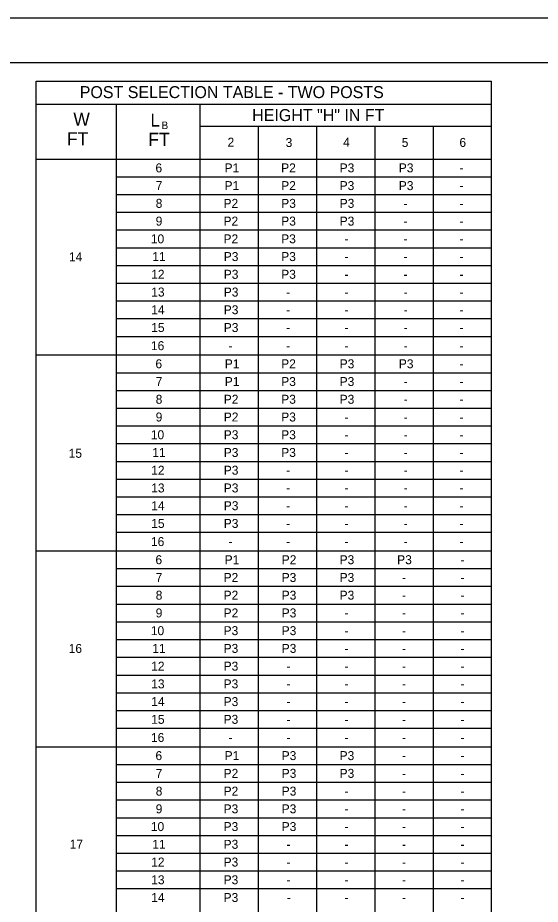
# Model space of a CAD drawing. Extents: x -2340 to 628, y -879 to 309.
# Drawn here: x -912.9 to -738, y -581.5 to -284.6 of the extents above; entities that cross this region are included whole.
import ezdxf

# ---------------------------------------------------------------- set-up
doc = ezdxf.new("R2010")
doc.units = 0
for name, color, linetype in [('Level 1', 7, 'Continuous'), ('Level 2', 7, 'Continuous'), ('Level 30', 7, 'Continuous'), ('PLT-BNDY', 7, 'Continuous')]:
    doc.layers.add(name, color=color, linetype=linetype)

msp = doc.modelspace()

# ---------------------------------------------------------------- linework, layer by layer
at = {"layer": 'Level 1'}
for p, q in [((-1077.39, -299.56), (-291.39, -299.56)), ((-906.65, -791.15), (-906.65, -305.86)), ((-906.65, -305.86), (-754.31, -305.86)), ((-754.31, -791.15), (-754.31, -305.86)), ((-906.65, -313.54), (-754.31, -313.54)), ((-879.85, -791.15), (-879.85, -313.54)), ((-851.84, -791.15), (-851.84, -313.54)), ((-832.34, -791.15), (-832.34, -320.88)), ((-812.83, -791.15), (-812.83, -320.88)), ((-793.32, -791.15), (-793.32, -320.88)), ((-773.81, -791.15), (-773.81, -320.88)), ((-906.65, -331.88), (-754.31, -331.88)), ((-813.5, -331.88), (-777.86, -331.88)), ((-879.85, -337.82), (-754.31, -337.82)), ((-879.85, -343.76), (-754.31, -343.76)), ((-879.85, -349.7), (-754.31, -349.7)), ((-879.85, -355.64), (-754.31, -355.64)), ((-879.85, -361.58), (-754.31, -361.58)), ((-879.85, -367.52), (-754.31, -367.52)), ((-879.85, -373.46), (-754.31, -373.46)), ((-879.85, -379.4), (-754.31, -379.4)), ((-879.85, -385.34), (-754.31, -385.34)), ((-879.85, -391.28), (-754.31, -391.28)), ((-906.65, -397.49), (-754.31, -397.49)), ((-879.85, -403.43), (-754.31, -403.43)), ((-879.85, -409.37), (-754.31, -409.37)), ((-879.85, -415.31), (-754.31, -415.31)), ((-879.85, -421.25), (-754.31, -421.25)), ((-879.85, -427.19), (-754.31, -427.19)), ((-879.85, -433.13), (-754.31, -433.13)), ((-879.85, -439.07), (-754.31, -439.07)), ((-879.85, -445.01), (-754.31, -445.01)), ((-879.85, -450.95), (-754.31, -450.95)), ((-879.85, -456.89), (-754.31, -456.89)), ((-906.65, -463.1), (-754.31, -463.1)), ((-879.85, -469.04), (-754.31, -469.04)), ((-879.85, -474.98), (-754.31, -474.98)), ((-813.5, -474.98), (-777.86, -474.98)), ((-777.86, -474.98), (-754.31, -474.98)), ((-879.85, -480.92), (-754.31, -480.92)), ((-879.85, -486.86), (-754.31, -486.86)), ((-879.85, -492.8), (-754.31, -492.8)), ((-879.85, -498.74), (-754.31, -498.74)), ((-879.85, -504.68), (-754.31, -504.68)), ((-879.85, -510.62), (-754.31, -510.62)), ((-879.85, -516.56), (-754.31, -516.56)), ((-879.85, -522.5), (-754.31, -522.5)), ((-906.65, -528.71), (-754.31, -528.71)), ((-879.85, -534.65), (-754.31, -534.65)), ((-879.85, -540.59), (-754.31, -540.59)), ((-879.85, -546.53), (-754.31, -546.53)), ((-879.85, -552.47), (-754.31, -552.47)), ((-879.85, -558.41), (-754.31, -558.41)), ((-879.85, -564.35), (-754.31, -564.35)), ((-879.85, -570.29), (-754.31, -570.29)), ((-879.85, -576.23), (-754.31, -576.23))]:
    msp.add_line(p, q, dxfattribs=at)
at = {"layer": 'Level 2'}
msp.add_line((-851.84, -320.88), (-754.31, -320.88), dxfattribs=at)
at = {"layer": 'PLT-BNDY'}
msp.add_lwpolyline([(-1117.39, -284.56), (-276.39, -284.56), (-276.39, -878.56), (-1117.39, -878.56)], close=True, dxfattribs=at)

# ---------------------------------------------------------------- texts
at = {"layer": 'Level 1'}
for s, height, p in [('POST SELECTION TABLE - TWO POSTS', 4.003, (-892.12, -311.48)), ('W', 4.37, (-894.25, -320.74)), ('L', 4.3, (-868.46, -321.01)), ('HEIGHT "H" IN FT', 4.003, (-834.42, -319.17)), ('B', 2.5, (-864.76, -321.84)), ('FT', 4.375, (-896.42, -327.3)), ('FT', 4.375, (-869.16, -327.47)), ('2', 3, (-842.66, -327.74)), ('3', 3, (-823.22, -327.84)), ('4', 3, (-803.98, -327.74)), ('5', 3, (-784.39, -327.84)), ('6', 3, (-765.08, -327.82)), ('P1', 3, (-843.67, -336.35)), ('P2', 3, (-824.72, -336.35)), ('P3', 3, (-805.15, -336.35)), ('P3', 3, (-785.37, -336.35)), ('-', 3, (-765.05, -336.35)), ('P1', 3, (-843.67, -342.29)), ('P2', 3, (-824.71, -342.29)), ('P3', 3, (-805.15, -342.29)), ('P3', 3, (-785.37, -342.29)), ('-', 3, (-765.05, -342.29)), ('P2', 3, (-844.01, -348.23)), ('P3', 3, (-824.71, -348.23)), ('P3', 3, (-805.15, -348.23)), ('-', 3, (-783.75, -348.23)), ('-', 3, (-765.05, -348.23)), ('P2', 3, (-844.01, -354.17)), ('P3', 3, (-824.71, -354.17)), ('P3', 3, (-805.15, -354.17)), ('-', 3, (-783.75, -354.17)), ('-', 3, (-765.05, -354.17)), ('P2', 3, (-844.01, -360.11)), ('P3', 3, (-824.71, -360.11)), ('-', 3, (-803.53, -360.11)), ('-', 3, (-783.75, -360.11)), ('-', 3, (-765.05, -360.11)), ('14', 3, (-895.73, -366.13)), ('P3', 3, (-843.93, -366.05)), ('P3', 3, (-824.71, -366.05)), ('-', 3, (-803.53, -366.05)), ('-', 3, (-783.75, -366.05)), ('-', 3, (-765.05, -366.05)), ('P3', 3, (-843.93, -371.99)), ('P3', 3, (-824.71, -371.99)), ('-', 3, (-803.53, -371.99)), ('-', 3, (-783.75, -371.99)), ('-', 3, (-765.05, -371.99)), ('P3', 3, (-843.93, -377.93)), ('-', 3, (-823.09, -377.93)), ('-', 3, (-803.53, -377.93)), ('-', 3, (-783.74, -377.93)), ('-', 3, (-765.05, -377.93)), ('P3', 3, (-843.93, -383.87)), ('-', 3, (-823.09, -383.87)), ('-', 3, (-803.53, -383.87)), ('-', 3, (-783.74, -383.87)), ('-', 3, (-765.05, -383.87)), ('P3', 3, (-843.93, -389.81)), ('-', 3, (-823.09, -389.81)), ('-', 3, (-803.53, -389.81)), ('-', 3, (-783.74, -389.81)), ('-', 3, (-765.05, -389.81)), ('-', 3, (-842.31, -395.89)), ('-', 3, (-823.09, -395.89)), ('-', 3, (-803.53, -395.89)), ('-', 3, (-783.74, -395.89)), ('-', 3, (-765.05, -395.89)), ('P1', 3, (-843.59, -401.96)), ('P2', 3, (-824.71, -401.96)), ('P3', 3, (-805.15, -401.96)), ('P3', 3, (-785.36, -401.96)), ('-', 3, (-765.05, -401.96)), ('P1', 3, (-843.59, -407.9)), ('P3', 3, (-824.71, -407.9)), ('P3', 3, (-805.15, -407.9)), ('-', 3, (-783.74, -407.9)), ('-', 3, (-765.05, -407.9)), ('P2', 3, (-843.93, -413.84)), ('P3', 3, (-824.71, -413.84)), ('P3', 3, (-805.15, -413.84)), ('-', 3, (-783.74, -413.84)), ('-', 3, (-765.05, -413.84)), ('P2', 3, (-843.93, -419.78)), ('P3', 3, (-824.71, -419.78)), ('-', 3, (-803.53, -419.78)), ('-', 3, (-783.74, -419.78)), ('-', 3, (-765.05, -419.78)), ('P3', 3, (-843.93, -425.72)), ('P3', 3, (-824.71, -425.72)), ('-', 3, (-803.53, -425.72)), ('-', 3, (-783.74, -425.72)), ('-', 3, (-765.05, -425.72)), ('15', 3, (-895.82, -431.93)), ('P3', 3, (-843.93, -431.66)), ('P3', 3, (-824.71, -431.66)), ('-', 3, (-803.53, -431.66)), ('-', 3, (-783.74, -431.66)), ('-', 3, (-765.05, -431.66)), ('P3', 3, (-843.93, -437.6)), ('-', 3, (-823.09, -437.6)), ('-', 3, (-803.53, -437.6)), ('-', 3, (-783.74, -437.6)), ('-', 3, (-765.05, -437.6)), ('P3', 3, (-843.93, -443.54)), ('-', 3, (-823.09, -443.54)), ('-', 3, (-803.53, -443.54)), ('-', 3, (-783.74, -443.54)), ('-', 3, (-765.05, -443.54)), ('P3', 3, (-843.93, -449.48)), ('-', 3, (-823.09, -449.48)), ('-', 3, (-803.53, -449.48)), ('-', 3, (-783.74, -449.48)), ('-', 3, (-765.05, -449.48)), ('P3', 3, (-843.93, -455.42)), ('-', 3, (-823.09, -455.42)), ('-', 3, (-803.53, -455.42)), ('-', 3, (-783.74, -455.42)), ('-', 3, (-765.05, -455.42)), ('-', 3, (-842.31, -461.5)), ('-', 3, (-823.09, -461.5)), ('-', 3, (-803.53, -461.5)), ('-', 3, (-783.74, -461.5)), ('-', 3, (-765.05, -461.5)), ('P1', 3, (-843.64, -467.57)), ('P2', 3, (-824.55, -467.57)), ('P3', 3, (-805.17, -467.57)), ('P3', 3, (-785.91, -467.57)), ('-', 3, (-764.69, -467.57)), ('P2', 3, (-843.98, -473.51)), ('P3', 3, (-824.55, -473.51)), ('P3', 3, (-805.17, -473.51)), ('-', 3, (-784.29, -473.51)), ('-', 3, (-764.69, -473.51)), ('P2', 3, (-843.98, -479.45)), ('P3', 3, (-824.55, -479.45)), ('P3', 3, (-805.17, -479.45)), ('-', 3, (-784.29, -479.45)), ('-', 3, (-764.69, -479.45)), ('P2', 3, (-843.98, -485.39)), ('P3', 3, (-824.55, -485.39)), ('-', 3, (-803.55, -485.39)), ('-', 3, (-784.29, -485.39)), ('-', 3, (-764.69, -485.39)), ('P3', 3, (-843.98, -491.33)), ('P3', 3, (-824.55, -491.33)), ('-', 3, (-803.55, -491.33)), ('-', 3, (-784.29, -491.33)), ('-', 3, (-764.69, -491.33)), ('16', 3, (-895.81, -497.29)), ('P3', 3, (-843.98, -497.27)), ('P3', 3, (-824.55, -497.27)), ('-', 3, (-803.55, -497.27)), ('-', 3, (-784.29, -497.27)), ('-', 3, (-764.69, -497.27)), ('P3', 3, (-843.98, -503.21)), ('-', 3, (-822.94, -503.21)), ('-', 3, (-803.55, -503.21)), ('-', 3, (-784.29, -503.21)), ('-', 3, (-764.69, -503.21)), ('P3', 3, (-843.98, -509.15)), ('-', 3, (-822.94, -509.15)), ('-', 3, (-803.55, -509.15)), ('-', 3, (-784.29, -509.15)), ('-', 3, (-764.69, -509.15)), ('P3', 3, (-843.98, -515.09)), ('-', 3, (-822.94, -515.09)), ('-', 3, (-803.55, -515.09)), ('-', 3, (-784.29, -515.09)), ('-', 3, (-764.69, -515.09)), ('P3', 3, (-843.98, -521.03)), ('-', 3, (-822.94, -521.03)), ('-', 3, (-803.55, -521.03)), ('-', 3, (-784.29, -521.03)), ('-', 3, (-764.69, -521.03)), ('-', 3, (-842.36, -527.11)), ('-', 3, (-822.94, -527.11)), ('-', 3, (-803.55, -527.11)), ('-', 3, (-784.29, -527.11)), ('-', 3, (-764.69, -527.11)), ('P1', 3, (-843.64, -533.18)), ('P3', 3, (-824.55, -533.18)), ('P3', 3, (-805.17, -533.18)), ('-', 3, (-784.29, -533.18)), ('-', 3, (-764.69, -533.18)), ('P2', 3, (-843.98, -539.12)), ('P3', 3, (-824.55, -539.12)), ('P3', 3, (-805.17, -539.12)), ('-', 3, (-784.29, -539.12)), ('-', 3, (-764.69, -539.12)), ('P2', 3, (-843.98, -545.06)), ('P3', 3, (-824.55, -545.06)), ('-', 3, (-803.55, -545.06)), ('-', 3, (-784.29, -545.06)), ('-', 3, (-764.69, -545.06)), ('P3', 3, (-843.98, -551)), ('P3', 3, (-824.55, -551)), ('-', 3, (-803.55, -551)), ('-', 3, (-784.29, -551)), ('-', 3, (-764.69, -551)), ('P3', 3, (-843.98, -556.94)), ('P3', 3, (-824.55, -556.94)), ('-', 3, (-803.55, -556.94)), ('-', 3, (-784.29, -556.94)), ('-', 3, (-764.69, -556.94)), ('17', 3, (-895.46, -562.81)), ('P3', 3, (-843.98, -562.88)), ('-', 3, (-822.94, -562.88)), ('-', 3, (-803.55, -562.88)), ('-', 3, (-784.29, -562.88)), ('-', 3, (-764.69, -562.88)), ('P3', 3, (-843.98, -568.82)), ('-', 3, (-822.94, -568.82)), ('-', 3, (-803.55, -568.82)), ('-', 3, (-784.29, -568.82)), ('-', 3, (-764.69, -568.82)), ('P3', 3, (-843.98, -574.76)), ('-', 3, (-822.91, -574.76)), ('-', 3, (-803.55, -574.76)), ('-', 3, (-784.29, -574.76)), ('-', 3, (-764.69, -574.76)), ('P3', 3, (-843.98, -580.7)), ('-', 3, (-822.86, -580.7)), ('-', 3, (-803.55, -580.7)), ('-', 3, (-784.29, -580.7)), ('-', 3, (-764.69, -580.7))]:
    msp.add_text(s, height=height, dxfattribs=at).set_placement(p)
at = {"layer": 'Level 2'}
for s, p in [('7', (-866.7, -342.29)), ('8', (-866.7, -348.23)), ('9', (-866.71, -354.17)), ('10', (-868.33, -360.11)), ('11', (-867.85, -366.05)), ('12', (-868.2, -371.99)), ('13', (-868.2, -377.93)), ('14', (-868.2, -383.87)), ('15', (-868.2, -389.81)), ('16', (-868.28, -395.89)), ('7', (-866.7, -407.9)), ('8', (-866.7, -413.84)), ('9', (-866.71, -419.78)), ('10', (-868.33, -425.72)), ('11', (-867.85, -431.66)), ('12', (-868.2, -437.6)), ('13', (-868.2, -443.54)), ('14', (-868.2, -449.48)), ('15', (-868.2, -455.42)), ('16', (-868.28, -461.5)), ('7', (-866.7, -473.51)), ('8', (-866.7, -479.45)), ('9', (-866.71, -485.39)), ('10', (-868.33, -491.33)), ('11', (-867.85, -497.27)), ('12', (-868.2, -503.21)), ('13', (-868.2, -509.15)), ('14', (-868.2, -515.09)), ('15', (-868.2, -521.03)), ('16', (-868.28, -527.11)), ('7', (-866.7, -539.12)), ('8', (-866.7, -545.06)), ('9', (-866.71, -551)), ('10', (-868.33, -556.94)), ('11', (-867.85, -562.88)), ('12', (-868.2, -568.82)), ('13', (-868.2, -574.76)), ('14', (-868.2, -580.7))]:
    msp.add_text(s, height=3, dxfattribs=at).set_placement(p)
at = {"layer": 'Level 30'}
for p in [(-866.78, -336.35), (-866.78, -401.96), (-866.78, -467.57), (-866.78, -533.18)]:
    msp.add_text('6', height=3, dxfattribs=at).set_placement(p)

doc.saveas('drawing.dxf')
